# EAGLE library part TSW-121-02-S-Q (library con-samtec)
THROUGH-HOLE .025" SQ POST HEADER Source: Samtec TSW.pdf
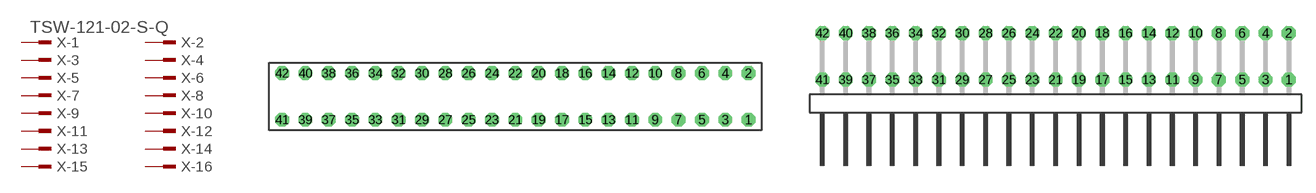
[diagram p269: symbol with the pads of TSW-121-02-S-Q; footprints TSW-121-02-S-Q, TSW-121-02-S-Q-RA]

Designator prefix X; gates -1=MPINV -2=MPIN -3=MPIN -4=MPIN -5=MPIN -6=MPIN -7=MPIN -8=MPIN -9=MPIN -10=MPIN -11=MPIN -12=MPIN -13=MPIN -14=MPIN -15=MPIN -16=MPIN -17=MPIN -18=MPIN -19=MPIN -20=MPIN -21=MPIN -22=MPIN -23=MPIN -24=MPIN -25=MPIN -26=MPIN -27=MPIN -28=MPIN -29=MPIN -30=MPIN -31=MPIN -32=MPIN -33=MPIN -34=MPIN -35=MPIN -36=MPIN -37=MPIN -38=MPIN -39=MPIN -40=MPIN -41=MPIN -42=MPIN

## TSW-121-02-S-Q (OC_FARNELL: unknown; OC_NEWARK: unknown)  [TSW-121-02-S-Q]
1  -1:1  pas
2  -2:1  pas
3  -3:1  pas
4  -4:1  pas
5  -5:1  pas
6  -6:1  pas
7  -7:1  pas
8  -8:1  pas
9  -9:1  pas
10  -10:1  pas
11  -11:1  pas
12  -12:1  pas
13  -13:1  pas
14  -14:1  pas
15  -15:1  pas
16  -16:1  pas
17  -17:1  pas
18  -18:1  pas
19  -19:1  pas
20  -20:1  pas
21  -21:1  pas
22  -22:1  pas
23  -23:1  pas
24  -24:1  pas
25  -25:1  pas
26  -26:1  pas
27  -27:1  pas
28  -28:1  pas
29  -29:1  pas
30  -30:1  pas
31  -31:1  pas
32  -32:1  pas
33  -33:1  pas
34  -34:1  pas
35  -35:1  pas
36  -36:1  pas
37  -37:1  pas
38  -38:1  pas
39  -39:1  pas
40  -40:1  pas
41  -41:1  pas
42  -42:1  pas

## TSW-121-02-S-Q-RA (OC_FARNELL: unknown; OC_NEWARK: unknown)  [TSW-121-02-S-Q-RA]
Pads as for TSW-121-02-S-Q

## Footprint TSW-121-02-S-Q (pad centres in mm)
THROUGH-HOLE .025" SQ POST HEADER Source: Samtec TSW.pdf
drill 1 pad 1.5 octagon: 1 25.4,-2.54; 2 25.4,2.54; 3 22.86,-2.54; 4 22.86,2.54; 5 20.32,-2.54; 6 20.32,2.54; 7 17.78,-2.54; 8 17.78,2.54; 9 15.24,-2.54; 10 15.24,2.54; 11 12.7,-2.54; 12 12.7,2.54; 13 10.16,-2.54; 14 10.16,2.54; 15 7.62,-2.54; 16 7.62,2.54; 17 5.08,-2.54; 18 5.08,2.54; 19 2.54,-2.54; 20 2.54,2.54; 21 0,-2.54; 22 0,2.54; 23 -2.54,-2.54; 24 -2.54,2.54; 25 -5.08,-2.54; 26 -5.08,2.54; 27 -7.62,-2.54; 28 -7.62,2.54; 29 -10.16,-2.54; 30 -10.16,2.54; 31 -12.7,-2.54; 32 -12.7,2.54; 33 -15.24,-2.54; 34 -15.24,2.54; 35 -17.78,-2.54; 36 -17.78,2.54; 37 -20.32,-2.54; 38 -20.32,2.54; 39 -22.86,-2.54; 40 -22.86,2.54; 41 -25.4,-2.54; 42 -25.4,2.54

## Footprint TSW-121-02-S-Q-RA (pad centres in mm)
THROUGH-HOLE .025" SQ POST HEADER Source: Samtec TSW.pdf
drill 1 pad 1.5 octagon: 1 25.4,1.524; 2 25.4,6.604; 3 22.86,1.524; 4 22.86,6.604; 5 20.32,1.524; 6 20.32,6.604; 7 17.78,1.524; 8 17.78,6.604; 9 15.24,1.524; 10 15.24,6.604; 11 12.7,1.524; 12 12.7,6.604; 13 10.16,1.524; 14 10.16,6.604; 15 7.62,1.524; 16 7.62,6.604; 17 5.08,1.524; 18 5.08,6.604; 19 2.54,1.524; 20 2.54,6.604; 21 0,1.524; 22 0,6.604; 23 -2.54,1.524; 24 -2.54,6.604; 25 -5.08,1.524; 26 -5.08,6.604; 27 -7.62,1.524; 28 -7.62,6.604; 29 -10.16,1.524; 30 -10.16,6.604; 31 -12.7,1.524; 32 -12.7,6.604; 33 -15.24,1.524; 34 -15.24,6.604; 35 -17.78,1.524; 36 -17.78,6.604; 37 -20.32,1.524; 38 -20.32,6.604; 39 -22.86,1.524; 40 -22.86,6.604; 41 -25.4,1.524; 42 -25.4,6.604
